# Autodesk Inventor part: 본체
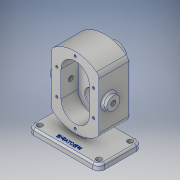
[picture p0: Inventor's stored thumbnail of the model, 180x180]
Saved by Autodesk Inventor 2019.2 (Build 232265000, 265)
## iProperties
Created: 2019-03
Part Number: 본체
Material: 알루미늄 6061
Document SubType Name: Modeling
Designer: User
Density: 2.7 g/cm^3
Appearance: 알루미늄 - 평지
Mass: 1187.12 g
Surface Area: 719.257 cm^2
Volume: 439.673 cm^3
Author: User
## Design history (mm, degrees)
sketch "스케치1"
  geometry: L1 (60, 36.5)-(-60, 36.5); L2 (-60, 36.5)-(-60, -36.5); L3 (-60, -36.5)-(60, -36.5); L4 (60, -36.5)-(60, 36.5); L5 (0, -51.1)-(0, 51.1) reference; L6 (-84, 0)-(84, 0) reference; 1 further point
  constraints: 8 end point, 2 parallel, 1 horizontal, 1 perpendicular, 2 other
  dimensions: "d0" = 120 distance of L2.end L3.end; "d1" = 73 distance of L1.end L2.end
extrude "돌출1" new body sketch "스케치1" distance "d2" = 10; taper "d3" = 0 deg
sketch "스케치3"
  geometry: L1 (20, 122.721)-(100, 122.721); L2 (100, 122.721)-(100, 33.279); L3 (100, 33.279)-(20, 33.279); L4 (20, 33.279)-(20, 122.721); L5 (60, -27.6)-(60, 165.6) reference; L6 (-24, 0)-(144, 0) reference; A1 r 60 centre (60, 78) between (100, 122.721) and (20, 122.721); A2 r 60 centre (60, 78) between (20, 33.279) and (100, 33.279); 1 further point
  constraints: 8 end point, 4 point on circle, 2 centre point, 2 parallel, 1 coincident, 1 horizontal, 1 perpendicular, 1 other
  dimensions: "d9" = 60 radius of A2; "d10" = 60 radius of A1; "d11" = 138 dimension on A1 L6; "d23" = 80 distance between parallel lines of L2 L4
extrude "돌출2" join sketch "스케치3" distance "d12" = 53; taper "d13" = 0 deg
sketch "스케치4"
  geometry: L1 (50, 6.5)-(0, 6.5); L2 (0, 6.5)-(0, -36.5); L3 (0, -36.5)-(50, -36.5); L4 (50, -36.5)-(50, 6.5); L5 (0, 36.5)-(0, -36.5) reference; L6 (0, -36.5)-(10, -36.5) reference; 1 further point
  constraints: 8 end point, 2 collinear, 2 parallel, 1 horizontal, 1 perpendicular
  dimensions: "d14" = 43 distance of L3.end L1.start; "d15" = 50 distance of L2.end L3.end
extrude "돌출3" join sketch "스케치4" stored distance "d16" = 12; taper "d17" = 0 deg
sketch "스케치5"
  geometry: L1 (0, 36.5)-(0, -36.5) reference; L2 (122.721, -36.5)-(33.279, -36.5) reference; C1 r 11 at (78, 0); 1 further point
  constraints: 1 centre point
  dimensions: "d18" = 22 diameter of C1; "d19" = 78 distance from line of C1.centre L1; "d20" = 36.5 distance from line of C1.centre L2
extrude "돌출4" join sketch "스케치5" stored distance "d21" = 96; taper "d22" = 0 deg
sketch "스케치6"
  geometry: L1 (-60, 100)-(-60, 56); L2 (-84, 100)-(-84, 56); L3 (-36, 56)-(-36, 100); L4 (-60, 174.383)-(-60, -45.544) reference; L5 (-144, 0)-(24, 0) reference; A1 r 24 centre (-60, 100) between (-36, 100) and (-84, 100); A2 r 24 centre (-60, 56) between (-84, 56) and (-36, 56); 2 further points
  constraints: 8 end point, 4 point on circle, 4 tangent, 2 centre point, 1 collinear, 1 midpoint, 1 parallel, 1 vertical
  dimensions: "d24" = 24 radius of A1; "d25" = 44 distance of L1.start L1.end; "d26" = 78 distance from line of L5 point (-60, 78)
extrude "돌출5" cut sketch "스케치6" distance "d27" = 29; taper "d28" = 0 deg
sketch "스케치7"
  geometry: L1 (60, 0)-(60, 192.078); L2 (0, 0)-(120, 0) reference; C1 r 19 at (60, 100)
  constraints: 2 end point, 1 centre point, 1 point on line, 1 vertical
  dimensions: "d29" = 38 diameter of C1; "d30" = 100 distance from line of L2 C1.centre
extrude "돌출6" join sketch "스케치7" distance "d31" = 17; taper "d32" = 0 deg
sketch "스케치8"
  geometry: C1 r 19 at (0, 0) reference; 2 further points
  constraints: 1 coincident
hole "구멍1" sketch "스케치8" at (0, 0) diameter "d33" = 17; stored, may be unused: countersink angle "d37" = 90 deg, drill point angle "d39" = 0 deg; dims "d34" = 6, "d35" = 28, "d36" = 7.3, "d38" = 26
sketch "스케치9"
  geometry: L1 (-60, 26.459)-(-60, 107.532); L2 (-120, 0)-(0, 0) reference; 4 further points
  constraints: 3 point on line, 2 end point, 1 midpoint, 1 vertical
  dimensions: "d40" = 44 distance of point (-60, 56) point (-60, 100); "d41" = 100 distance from line of L2 point (-60, 100)
hole "구멍2" sketch "스케치9" at (-60, 100), (-60, 56) diameter "d42" = 25; stored, may be unused: countersink angle "d46" = 90 deg, drill point angle "d48" = 0 deg; dims "d43" = 6, "d44" = 28, "d45" = 7.3, "d47" = 15
sketch "스케치10"
  geometry: C1 r 11 at (0, 0) reference; 2 further points
  constraints: 1 coincident
hole "구멍3" sketch "스케치10" at (0, 0) diameter "d49" = 8.376; stored, may be unused: countersink angle "d53" = 90 deg, drill point angle "d55" = 0 deg; dims "d50" = 27, "d51" = 28, "d52" = 7.3, "d54" = 27
sketch "스케치11"
  geometry: C1 r 11 at (0, 0) reference; 2 further points
  constraints: 1 coincident
hole "구멍4" sketch "스케치11" at (0, 0) diameter "d56" = 8.376; stored, may be unused: countersink angle "d60" = 90 deg, drill point angle "d62" = 0 deg; dims "d57" = 27, "d58" = 28, "d59" = 7.3, "d61" = 27
sketch "스케치12"
  geometry: L1 (-60, 100)-(-60, 56); L2 (-91, 100)-(-91, 56); L3 (-29, 56)-(-29, 100); L4 (-60, 0)-(-60, 154.262); L5 (-120, 0)-(0, 0) reference; A1 r 31 centre (-60, 100) between (-29, 100) and (-91, 100); A2 r 31 centre (-60, 56) between (-91, 56) and (-29, 56); 9 further points
  constraints: 10 end point, 6 coincident, 6 point on circle, 4 tangent, 2 centre point, 2 vertical, 1 collinear, 1 midpoint, 1 parallel
  dimensions: "d65" = 31 radius of A1; "d66" = 56 distance from line of L5 L1.end; "d67" = 100 distance from line of L5 L1.start
hole "구멍5" sketch "스케치12" at (-60, 131), (-91, 100), (-91, 56), (-60, 25), (-29, 100), (-29, 56) diameter "d68" = 4.134; stored, may be unused: countersink angle "d72" = 90 deg, drill point angle "d74" = 118 deg; dims "d69" = 10, "d70" = 28, "d71" = 7.3, "d73" = 12
fillet "모깎기1" dims "d75" = 10
sketch "스케치13"
  geometry: A1 r 10 centre (-50, -26.5) between (-60, -26.5) and (-50, -36.5) reference; A2 r 10 centre (-50, 26.5) between (-50, 36.5) and (-60, 26.5) reference; A3 r 10 centre (50, -26.5) between (50, -36.5) and (60, -26.5) reference; A4 r 10 centre (50, 26.5) between (60, 26.5) and (50, 36.5) reference; 5 further points
  constraints: 4 coincident
hole "구멍6" sketch "스케치13" at (-50, -26.5), (-50, 26.5), (50, -26.5), (50, 26.5) diameter "d76" = 9; stored, may be unused: countersink angle "d80" = 90 deg, drill point angle "d82" = 0 deg; dims "d77" = 10, "d78" = 28, "d79" = 7.3, "d81" = 10
fillet "모깎기2" dims "d83" = 0.5
chamfer "모따기2" distance "d87" = 1; stored, may be unused: second distance "d88" = 2, angle "d89" = 30 deg
fillet "모깎기3" dims "d90" = 3
fillet "모깎기4" dims "d91" = 3
fillet "모깎기5" dims "d92" = 3
fillet "모깎기6" dims "d93" = 10
fillet "모깎기7" dims "d94" = 3
fillet "모깎기8" dims "d95" = 3
fillet "모깎기9" dims "d96" = 3
sketch "스케치14"
  geometry: L1 (-60, 26.5)-(-60, -26.5) reference; L2 (-50, -36.5)-(50, -36.5) reference; 2 further points
  constraints: 1 other
  dimensions: "d97" = 60 distance from line of L1 point (0, -26.5); "d98" = 10 distance from line of L2 point (0, -26.5)
feature "엠보싱1" sketch "스케치14" dims "d0" = 120, "d1" = 73, "d99" = 0.5, "d100" = 0
chamfer "모따기3" distance "d101" = 0.7; stored, may be unused: second distance "d102" = 2, angle "d103" = 30 deg
node "솔리드1"
